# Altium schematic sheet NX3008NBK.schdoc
size 127 x 101 mm
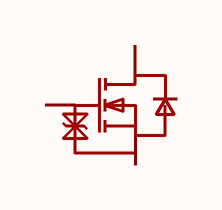
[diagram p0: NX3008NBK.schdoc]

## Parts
Q?  nx3008nbk  [SOT-23-3_L3.0-W1.7-P0.95-LS2.9-BR]  (value not drawn)

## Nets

Not connected (* = marked no-connect by the designer): Q? 1(G) 2(S) 3(D)

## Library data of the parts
Q? = nx3008nbk: 漏源电压(Vdss):30V;连续漏极电流(Id):850mA;导通电阻(RDS(on)):650mΩ@2.5V;耗散功率(Pd):360mW;阈值电压(Vgs(th)):1.2V@250uA;; Manufacturer: TECH PUBLIC(台舟); AddInBom: yes; ModelId: 89cb27a44ab2466697082bb9fd73a7d0; ModelName: SOT-23-3L_L2.9-W1.6-H1.1-LS2.8-P0.95; ModelTransform: 114.173,110.236,0,90,0,0,0,0,0; Drain to Source Voltage: 30V; Current - Continuous Drain(Id): 850mA; Pd - Power Dissipation: 360mW; Gate Charge(Qg): 5.2nC@4.5V; Input Capacitance(Ciss): 146pF; Reverse Transfer Capacitance (Crss@Vds): 14.8pF; Output Capacitance(Coss): 36.6pF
